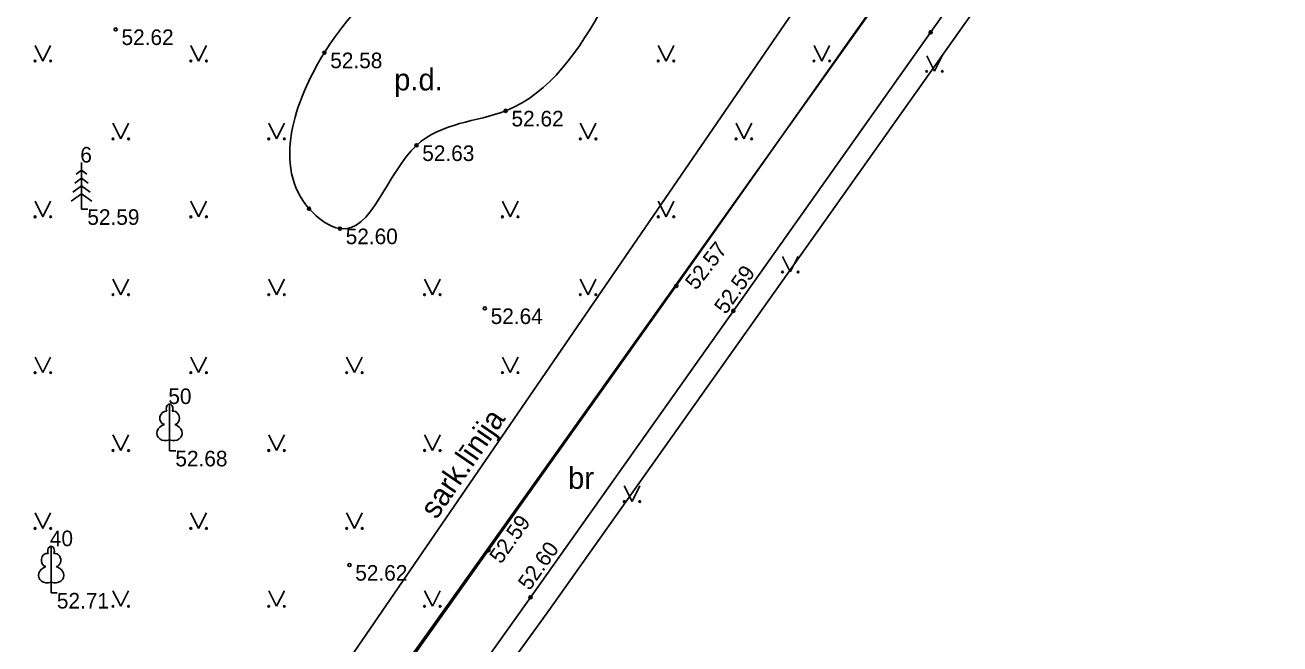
# Model space of a CAD drawing. Extents: x 619806 to 620082, y 405176 to 405386.
# Drawn here: x 620009.43 to 620049.7, y 405241.29 to 405261.15 of the extents above; entities that cross this region are included whole.
import ezdxf

# ---------------------------------------------------------------- set-up
doc = ezdxf.new("R2010")
doc.units = 0
for name, color, linetype in [('APGR_SARK_####_####_#', 7, 'Continuous'), ('APGR_SARK_IZNL_TKST_#', 7, 'Continuous'), ('CELI_CMAL_####_####_#', 7, 'Continuous'), ('CELI_CSEG_####_TKST_#', 7, 'Continuous'), ('RAMI_UZMR_####_####_#', 7, 'Continuous'), ('RELJ_AATZ_####_TKST_#', 7, 'Continuous'), ('RELJ_ELEM_####_####_#', 7, 'Continuous'), ('ROBZ_UZMR_####_####_#', 7, 'Continuous'), ('TERT_DIAM_####_TKST_#', 7, 'Continuous'), ('TERT_ELEM_####_####_#', 7, 'Continuous'), ('TERT_IZMT_####_TKST_#', 7, 'Continuous'), ('TERT_KONT_####_####_#', 7, 'Continuous')]:
    doc.layers.add(name, color=color, linetype=linetype)

msp = doc.modelspace()

# ---------------------------------------------------------------- linework, layer by layer
at = {"layer": 'APGR_SARK_####_####_#'}
msp.add_lwpolyline([(619976.198, 405343.424), (619987.786, 405326.116), (620001.138, 405307.928), (620014.265, 405290.061), (620015.405, 405288.784), (620016.767, 405287.746), (620041.487, 405272.379), (619990.053, 405197.403), (619990.053, 405197.403)], dxfattribs=at)
at = {"layer": 'CELI_CMAL_####_####_#'}
for points in [[(620017.253, 405234.372), (620024.304, 405244.304), (620030.33, 405252.781), (620037.106, 405262.397), (620044.255, 405272.554)], [(620047.008, 405270.595), (620045.914, 405271.411), (620038.491, 405260.919), (620032.163, 405251.981), (620025.649, 405242.786), (620018.938, 405233.375), (620011.736, 405223.226), (620012.557, 405222.608)]]:
    msp.add_lwpolyline(points, dxfattribs=at)
at = {"layer": 'RAMI_UZMR_####_####_#'}
msp.add_lwpolyline([(619874.687, 405324.979), (619926.719, 405349.544), (619966.669, 405369.042), (620021.738, 405292.03), (620049.703, 405275.476), (620026.189, 405242.287), (620012.147, 405222.917), (619996.603, 405200.928), (619989.997, 405199.173), (619982.328, 405199.155), (619922.669, 405233.014), (619882.137, 405255.756), (619859.084, 405268.056), (619820.646, 405290.715), (619813.744, 405295.206), (619820.645, 405298.752)], close=True, dxfattribs=at)
at = {"layer": 'RELJ_ELEM_####_####_#'}
for centre in [(620012.338, 405261.013), (620038.491, 405260.919), (620019.037, 405260.269), (620024.855, 405258.401), (620021.99, 405257.291), (620018.543, 405255.26), (620019.533, 405254.622), (620030.33, 405252.781), (620024.186, 405252.06), (620032.163, 405251.981), (620024.304, 405244.304), (620019.84, 405243.824), (620025.649, 405242.786)]:
    msp.add_circle(centre, 0.05, dxfattribs=at)
at = {"layer": 'ROBZ_UZMR_####_####_#'}
msp.add_line((620044.084, 405272.127), (619994.191, 405202.148), dxfattribs=at)
at = {"layer": 'TERT_ELEM_####_####_#'}
for p, q in [((620009.75, 405260.5), (620010, 405260)), ((620010, 405260), (620010.25, 405260.5)), ((620014.75, 405260.5), (620015, 405260)), ((620015, 405260), (620015.25, 405260.5)), ((620029.75, 405260.5), (620030, 405260)), ((620030, 405260), (620030.25, 405260.5)), ((620034.75, 405260.5), (620035, 405260)), ((620035, 405260), (620035.25, 405260.5)), ((620038.366, 405260.171), (620038.616, 405259.671)), ((620038.616, 405259.671), (620038.866, 405260.171)), ((620012.25, 405258), (620012.5, 405257.5)), ((620012.5, 405257.5), (620012.75, 405258)), ((620017.25, 405258), (620017.5, 405257.5)), ((620017.5, 405257.5), (620017.75, 405258)), ((620027.25, 405258), (620027.5, 405257.5)), ((620027.5, 405257.5), (620027.75, 405258)), ((620032.25, 405258), (620032.5, 405257.5)), ((620032.5, 405257.5), (620032.75, 405258)), ((620011.241, 405256.742), (620011.241, 405255.242)), ((620011.241, 405256.242), (620011.025, 405256.084)), ((620011.241, 405256.492), (620011.065, 405256.364)), ((620011.241, 405256.492), (620011.415, 405256.364)), ((620011.241, 405256.242), (620011.457, 405256.084)), ((620011.241, 405255.992), (620010.963, 405255.788)), ((620011.241, 405255.992), (620011.519, 405255.788)), ((620009.75, 405255.5), (620010, 405255)), ((620010, 405255), (620010.25, 405255.5)), ((620011.241, 405255.742), (620010.909, 405255.498)), ((620011.241, 405255.742), (620011.575, 405255.498)), ((620014.75, 405255.5), (620015, 405255)), ((620015, 405255), (620015.25, 405255.5)), ((620024.75, 405255.5), (620025, 405255)), ((620025, 405255), (620025.25, 405255.5)), ((620029.75, 405255.5), (620030, 405255)), ((620030, 405255), (620030.25, 405255.5)), ((620011.241, 405255.242), (620011.441, 405255.242)), ((620033.74, 405253.731), (620033.99, 405253.231)), ((620033.99, 405253.231), (620034.24, 405253.731)), ((620012.25, 405253), (620012.5, 405252.5)), ((620012.5, 405252.5), (620012.75, 405253)), ((620017.25, 405253), (620017.5, 405252.5)), ((620017.5, 405252.5), (620017.75, 405253)), ((620022.25, 405253), (620022.5, 405252.5)), ((620022.5, 405252.5), (620022.75, 405253)), ((620027.25, 405253), (620027.5, 405252.5)), ((620027.5, 405252.5), (620027.75, 405253)), ((620009.75, 405250.5), (620010, 405250)), ((620010, 405250), (620010.25, 405250.5)), ((620014.75, 405250.5), (620015, 405250)), ((620015, 405250), (620015.25, 405250.5)), ((620019.75, 405250.5), (620020, 405250)), ((620020, 405250), (620020.25, 405250.5)), ((620024.75, 405250.5), (620025, 405250)), ((620025, 405250), (620025.25, 405250.5)), ((620012.25, 405248), (620012.5, 405247.5)), ((620012.5, 405247.5), (620012.75, 405248)), ((620014.066, 405247.839), (620014.066, 405247.492)), ((620017.25, 405248), (620017.5, 405247.5)), ((620017.5, 405247.5), (620017.75, 405248)), ((620022.25, 405248), (620022.5, 405247.5)), ((620022.5, 405247.5), (620022.75, 405248)), ((620014.066, 405247.492), (620014.266, 405247.492)), ((620028.66, 405246.362), (620028.91, 405245.862)), ((620028.91, 405245.862), (620029.16, 405246.362)), ((620009.75, 405245.5), (620010, 405245)), ((620010, 405245), (620010.25, 405245.5)), ((620014.75, 405245.5), (620015, 405245)), ((620015, 405245), (620015.25, 405245.5)), ((620019.75, 405245.5), (620020, 405245)), ((620020, 405245), (620020.25, 405245.5)), ((620010.263, 405243.277), (620010.263, 405242.93)), ((620010.263, 405242.93), (620010.463, 405242.93)), ((620012.25, 405243), (620012.5, 405242.5)), ((620012.5, 405242.5), (620012.75, 405243)), ((620017.25, 405243), (620017.5, 405242.5)), ((620017.5, 405242.5), (620017.75, 405243)), ((620022.25, 405243), (620022.5, 405242.5)), ((620022.5, 405242.5), (620022.75, 405243))]:
    msp.add_line(p, q, dxfattribs=at)
for points in [[(620014.066, 405248.992), (620014.066, 405247.839)], [(620014.156, 405248.76), (620014.155, 405248.761)], [(620010.263, 405244.43), (620010.263, 405243.277)], [(620010.353, 405244.198), (620010.352, 405244.199)]]:
    msp.add_lwpolyline(points, dxfattribs=at)
for centre, radius in [((620009.75, 405260), 0.028), ((620010.25, 405260), 0.0263), ((620014.75, 405260), 0.028), ((620015.25, 405260), 0.0263), ((620029.75, 405260), 0.028), ((620030.25, 405260), 0.0263), ((620034.75, 405260), 0.028), ((620035.25, 405260), 0.0263), ((620038.366, 405259.67), 0.028), ((620038.866, 405259.67), 0.0263), ((620012.25, 405257.5), 0.028), ((620012.75, 405257.5), 0.0263), ((620017.25, 405257.5), 0.028), ((620017.75, 405257.5), 0.0263), ((620027.25, 405257.5), 0.028), ((620027.75, 405257.5), 0.0263), ((620032.25, 405257.5), 0.028), ((620032.75, 405257.5), 0.0263), ((620009.75, 405255), 0.028), ((620010.25, 405255), 0.0263), ((620014.75, 405255), 0.028), ((620015.25, 405255), 0.0263), ((620024.75, 405255), 0.028), ((620025.25, 405255), 0.0263), ((620029.75, 405255), 0.028), ((620030.25, 405255), 0.0263), ((620033.739, 405253.23), 0.028), ((620034.239, 405253.23), 0.0263), ((620012.25, 405252.5), 0.028), ((620012.75, 405252.5), 0.0263), ((620017.25, 405252.5), 0.028), ((620017.75, 405252.5), 0.0263), ((620022.25, 405252.5), 0.028), ((620022.75, 405252.5), 0.0263), ((620027.25, 405252.5), 0.028), ((620027.75, 405252.5), 0.0263), ((620009.75, 405250), 0.028), ((620010.25, 405250), 0.0263), ((620014.75, 405250), 0.028), ((620015.25, 405250), 0.0263), ((620019.75, 405250), 0.028), ((620020.25, 405250), 0.0263), ((620024.75, 405250), 0.028), ((620025.25, 405250), 0.0263), ((620012.25, 405247.5), 0.028), ((620012.75, 405247.5), 0.0263), ((620017.25, 405247.5), 0.028), ((620017.75, 405247.5), 0.0263), ((620022.25, 405247.5), 0.028), ((620022.75, 405247.5), 0.0263), ((620028.659, 405245.862), 0.028), ((620029.159, 405245.862), 0.0263), ((620009.75, 405245), 0.028), ((620010.25, 405245), 0.0263), ((620014.75, 405245), 0.028), ((620015.25, 405245), 0.0263), ((620019.75, 405245), 0.028), ((620020.25, 405245), 0.0263), ((620012.25, 405242.5), 0.028), ((620012.75, 405242.5), 0.0263), ((620017.25, 405242.5), 0.028), ((620017.75, 405242.5), 0.0263), ((620022.25, 405242.5), 0.028), ((620022.75, 405242.5), 0.0263)]:
    msp.add_circle(centre, radius, dxfattribs=at)
for centre, major_axis, ratio, start_param, end_param in [((620014.066, 405248.842), (0, -0.15), 0.707107, 3.14537, 5.287485), ((620014.066, 405248.842), (0, -0.15), 0.707107, 0.995701, 3.137816), ((620013.938, 405248.547), (-0.039, -0.212), 0.861323, 3.141593, 6.283185), ((620014.194, 405248.547), (0.039, -0.212), 0.861323, 0, 3.141593), ((620013.976, 405248.085), (0.307, 0.095), 0.814445, 1.570796, 4.752015), ((620014.156, 405248.085), (-0.307, 0.095), 0.814445, 1.531171, 4.712389), ((620010.135, 405243.985), (-0.039, -0.212), 0.861323, 3.141593, 6.283185), ((620010.263, 405244.28), (0, -0.15), 0.707107, 3.14537, 5.287485), ((620010.263, 405244.28), (0, -0.15), 0.707107, 0.995701, 3.137816), ((620010.391, 405243.985), (0.039, -0.212), 0.861323, 0, 3.141593), ((620010.173, 405243.523), (0.307, 0.095), 0.814445, 1.570796, 4.752015), ((620010.353, 405243.523), (-0.307, 0.095), 0.814445, 1.531171, 4.712389)]:
    msp.add_ellipse(centre, major_axis=major_axis, ratio=ratio, start_param=start_param, end_param=end_param, dxfattribs=at)
at = {"layer": 'TERT_KONT_####_####_#'}
msp.add_spline([(620024.879, 405268.534), (620024.528, 405270.63), (620022.864, 405273.577), (620024.144, 405274.754), (620025.797, 405273.946), (620028.415, 405270.906), (620029.557, 405266.838), (620028.016, 405261.799), (620024.855, 405258.401), (620021.99, 405257.291), (620019.533, 405254.622), (620018.543, 405255.26), (620019.037, 405260.269), (620022.413, 405263.752), (620024.845, 405266.647), (620024.934, 405267.871), (620024.91, 405268.33)], degree=3, dxfattribs=at)

# ---------------------------------------------------------------- texts
at = {"layer": 'APGR_SARK_IZNL_TKST_#'}
msp.add_text('sark.līnija', height=0.7, rotation=55.5499, dxfattribs=at).set_placement((620022.631, 405245.263))
at = {"layer": 'CELI_CSEG_####_TKST_#'}
msp.add_text('br', height=0.7, dxfattribs=at).set_placement((620026.857, 405246.269))
at = {"layer": 'RELJ_AATZ_####_TKST_#'}
for s, p in [(' 52.62', (620012.338, 405260.513)), (' 52.58', (620019.037, 405259.769)), (' 52.62', (620024.855, 405257.901)), (' 52.63', (620021.99, 405256.791)), (' 52.59', (620011.241, 405254.742)), (' 52.60', (620019.533, 405254.122)), (' 52.64', (620024.186, 405251.56)), (' 52.68', (620014.066, 405246.992)), (' 52.62', (620019.84, 405243.324)), (' 52.71', (620010.263, 405242.43))]:
    msp.add_text(s, height=0.5, dxfattribs=at).set_placement(p)
for s, rotation, p in [(' 52.57', 52.2419, (620030.854, 405252.475)), (' 52.59', 54.702, (620031.81, 405251.692)), (' 52.59', 54.5923, (620024.594, 405243.683)), (' 52.60', 54.6852, (620025.512, 405242.829))]:
    msp.add_text(s, height=0.5, rotation=rotation, dxfattribs=at).set_placement(p)
at = {"layer": 'TERT_DIAM_####_TKST_#'}
for s, p in [(' 6', (620011.016, 405256.742)), (' 50', (620013.841, 405248.992)), (' 40', (620010.038, 405244.43))]:
    msp.add_text(s, height=0.5, dxfattribs=at).set_placement(p)
at = {"layer": 'TERT_IZMT_####_TKST_#'}
msp.add_text('p.d.', height=0.7, dxfattribs=at).set_placement((620021.275, 405259.056))

doc.saveas('drawing.dxf')
